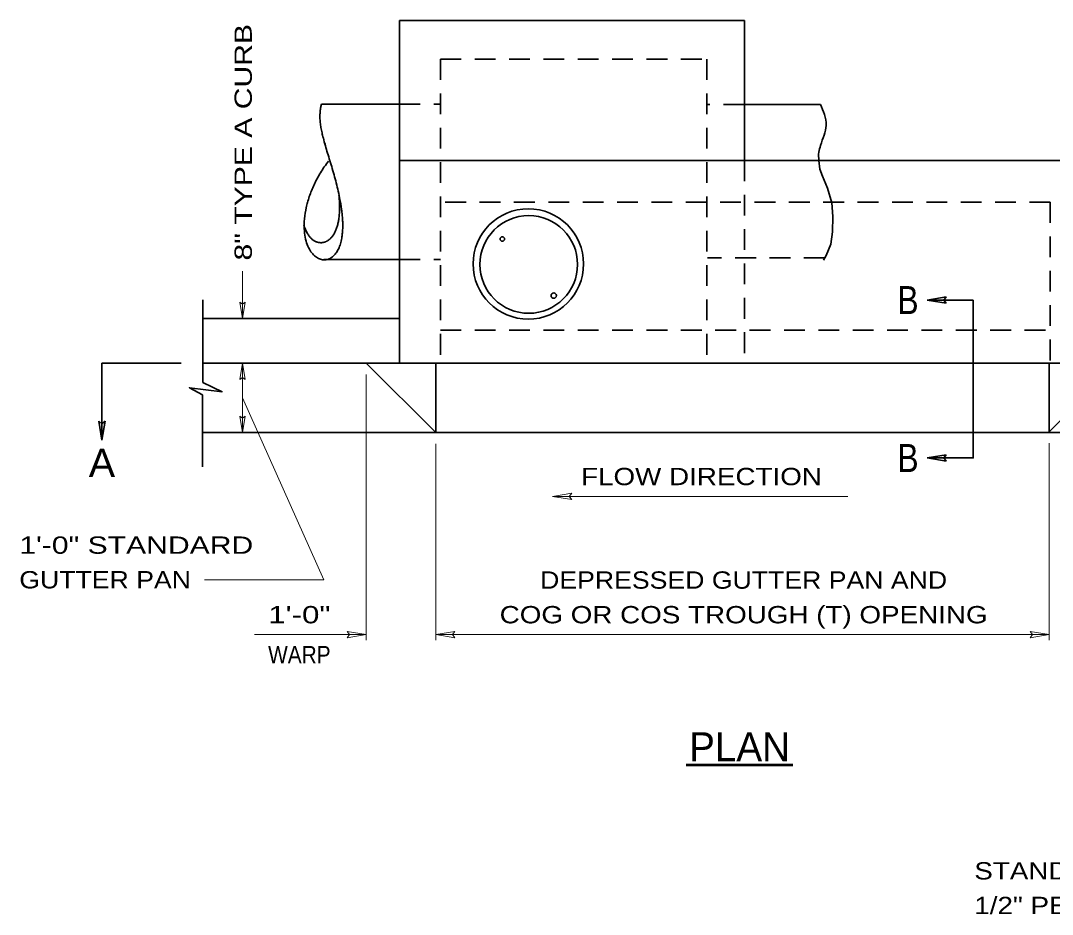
# Model space of a CAD drawing. Extents: x 16.6 to 31.7, y 5.4 to 26.
# Drawn here: x 16.65 to 24.24, y 13.28 to 19.86 of the extents above; entities that cross this region are included whole.
import ezdxf
from ezdxf.enums import TextEntityAlignment as Align

# ---------------------------------------------------------------- set-up
doc = ezdxf.new("R2010")
doc.units = 0
doc.header["$LTSCALE"] = 0.051
doc.linetypes.add('LONG_DASHED', pattern=[7.5, 6, -1.5])
doc.linetypes.add('MEDIUM_DASHED', pattern=[4.5, 3, -1.5])
for name, color, linetype, lineweight in [('1', 7, 'Continuous', 35), ('10', 7, 'Continuous', 13), ('12', 7, 'Continuous', 53), ('13', 7, 'Continuous', 53)]:
    doc.layers.add(name, color=color, linetype=linetype, lineweight=lineweight)

msp = doc.modelspace()

# ---------------------------------------------------------------- linework, layer by layer
at = {"layer": '1'}
for p, q in [((19.43833, 17.33783), (19.43833, 19.85942)), ((19.43833, 19.85942), (21.97725, 19.85942)), ((21.97725, 19.85942), (21.97725, 18.82992)), ((18.86417, 19.245), (19.43833, 19.245)), ((22.53767, 19.24225), (21.97725, 19.24225)), ((24.48625, 18.82992), (19.43833, 18.82992)), ((18.88275, 18.09975), (19.43833, 18.09975)), ((17.99208, 17.19558), (17.99208, 17.80275)), ((17.99208, 17.6655), (19.43833, 17.6655)), ((17.99208, 17.33783), (25.65375, 17.33783)), ((19.70542, 16.82675), (19.19433, 17.33783)), ((19.70542, 17.33783), (19.70542, 16.82675)), ((24.22067, 16.8315), (24.22067, 17.33783)), ((24.22067, 16.8315), (24.727, 17.33783)), ((17.98792, 16.57325), (17.98792, 17.10358)), ((25.65333, 16.82675), (17.98792, 16.82675))]:
    msp.add_line(p, q, dxfattribs=at)
at = {"layer": '1', "linetype": 'MEDIUM_DASHED'}
for p, q in [((19.73942, 19.57683), (19.73942, 17.33783)), ((19.43833, 19.245), (19.73942, 19.245)), ((21.97725, 19.24225), (21.702, 19.24225)), ((21.97725, 18.82992), (21.97725, 17.33783)), ((24.22942, 18.523), (19.73942, 18.523)), ((24.22942, 18.523), (24.22942, 17.33783)), ((19.43833, 18.09975), (19.73942, 18.09975)), ((22.56925, 18.11225), (21.70675, 18.11225)), ((19.73942, 17.5815), (24.22992, 17.5815))]:
    msp.add_line(p, q, dxfattribs=at)
msp.add_lwpolyline([(19.73942, 19.57683), (21.702, 19.57683), (21.702, 17.33783)], dxfattribs=at)
at = {"layer": '1', "linetype": 'LONG_DASHED'}
msp.add_lwpolyline([(22.52542, 18.8285), (22.53308, 18.765), (22.5535, 18.71408), (22.58925, 18.62508), (22.62242, 18.51833), (22.6275, 18.41658), (22.625, 18.30475), (22.61475, 18.21317), (22.579, 18.12925), (22.55958, 18.09533)], dxfattribs=at)
at = {"layer": '1'}
for centre, radius in [((20.38721, 18.06792), 0.40638), ((20.38983, 18.06417), 0.35949), ((20.19567, 18.25133), 0.0165), ((20.57408, 17.83454), 0.01952)]:
    msp.add_circle(centre, radius, dxfattribs=at)
for points in [[(18.86417, 19.245), (18.827, 19.09358), (18.91483, 18.85925), (19.1595, 18.28192), (19.16158, 17.88358), (18.57408, 17.913), (18.71633, 18.56783), (18.9165, 18.82575)], [(18.99325, 18.574), (18.99725, 18.53717), (19.00642, 18.39342), (18.98508, 18.274), (18.92517, 18.20125), (18.83642, 18.19292), (18.76317, 18.26392), (18.73367, 18.35692)]]:
    msp.add_open_spline(points, degree=6, dxfattribs=at)
msp.add_spline([(22.53767, 19.24225), (22.56625, 19.16925), (22.579, 19.08792), (22.56367, 19.01667), (22.53817, 18.94042), (22.52542, 18.89208), (22.52542, 18.8285)], degree=3, dxfattribs=at)
at = {"layer": '1', "lineweight": 13}
msp.add_open_spline([(18.89275, 18.95458), (18.89292, 18.95483), (18.89317, 18.95508), (18.89333, 18.95533), (18.8935, 18.95558), (18.89375, 18.95583), (18.89392, 18.95608)], degree=6, dxfattribs=at)
at = {"layer": '10'}
for p, q in [((18.28317, 17.6655), (18.28317, 18.01367)), ((18.26317, 17.7855), (18.28317, 17.6655)), ((18.26317, 17.7855), (18.28317, 17.7705)), ((18.30317, 17.7855), (18.28317, 17.6655)), ((18.30317, 17.7855), (18.28317, 17.7705)), ((18.26317, 17.21783), (18.28317, 17.33783)), ((18.30317, 17.21783), (18.28317, 17.33783)), ((18.28317, 16.82675), (18.28317, 17.33783)), ((19.19433, 15.29667), (19.19433, 17.2545)), ((18.26317, 17.21783), (18.28317, 17.23283)), ((18.30317, 17.21783), (18.28317, 17.23283)), ((18.26317, 16.94675), (18.28317, 16.82675)), ((18.26317, 16.94675), (18.28317, 16.93175)), ((18.30317, 16.94675), (18.28317, 16.82675)), ((18.30317, 16.94675), (18.28317, 16.93175)), ((19.70542, 15.29667), (19.70542, 16.74342)), ((24.22067, 15.29667), (24.22067, 16.74817)), ((20.70617, 16.37933), (20.56625, 16.35558)), ((20.70633, 16.33267), (20.56625, 16.35558)), ((20.56625, 16.35558), (22.73933, 16.35558)), ((20.70617, 16.37933), (20.68875, 16.356)), ((20.70633, 16.33267), (20.68875, 16.356)), ((19.05433, 15.36167), (19.19433, 15.33833)), ((19.05433, 15.36167), (19.07183, 15.33833)), ((19.84542, 15.3615), (19.70542, 15.33833)), ((19.84542, 15.3615), (19.82792, 15.33825)), ((24.08075, 15.36183), (24.22075, 15.33833)), ((24.08075, 15.36183), (24.09825, 15.33842)), ((19.19433, 15.33833), (18.3725, 15.33833)), ((19.05433, 15.315), (19.19433, 15.33833)), ((19.05433, 15.315), (19.07183, 15.33833)), ((19.84542, 15.31483), (19.70542, 15.33833)), ((24.22075, 15.33833), (19.70542, 15.33833)), ((19.84542, 15.31483), (19.82792, 15.33825)), ((24.08075, 15.31517), (24.09825, 15.33842)), ((24.08075, 15.31517), (24.22075, 15.33833))]:
    msp.add_line(p, q, dxfattribs=at)
at = {"layer": '10', "lineweight": 35}
for p, q in [((23.4625, 17.82508), (23.3225, 17.80175)), ((23.4625, 17.82508), (23.3225, 17.80175)), ((23.66267, 17.80175), (23.3225, 17.80175)), ((23.4625, 17.77842), (23.3225, 17.80175)), ((23.4625, 17.77842), (23.3225, 17.80175)), ((23.4625, 17.82508), (23.445, 17.80175)), ((23.4625, 17.82508), (23.445, 17.80175)), ((23.4625, 17.77842), (23.445, 17.80175)), ((23.4625, 17.77842), (23.445, 17.80175)), ((17.24842, 17.33783), (17.83275, 17.33783)), ((17.24842, 17.33783), (17.24842, 16.76925)), ((17.22508, 16.90925), (17.24842, 16.76925)), ((17.22508, 16.90925), (17.24842, 16.89175)), ((17.27175, 16.90925), (17.24842, 16.76925)), ((17.27175, 16.90925), (17.24842, 16.89175)), ((23.4625, 16.66242), (23.3225, 16.63908)), ((23.4625, 16.61575), (23.3225, 16.63908)), ((23.4625, 16.66242), (23.445, 16.63908)), ((23.4625, 16.61575), (23.445, 16.63908))]:
    msp.add_line(p, q, dxfattribs=at)
for points in [[(23.66267, 17.80175), (23.66267, 16.63908), (23.3225, 16.63908)], [(17.98792, 17.10358), (17.89267, 17.15592), (18.13308, 17.12658), (17.99208, 17.19558)]]:
    msp.add_lwpolyline(points, dxfattribs=at)
at = {"layer": '10'}
msp.add_lwpolyline([(18.28317, 17.08225), (18.88208, 15.74258), (18.00225, 15.74258)], dxfattribs=at)
at = {"layer": '12'}
msp.add_line((21.55, 14.37992), (22.33433, 14.37992), dxfattribs=at)

# ---------------------------------------------------------------- texts
at = {"layer": '12', "width": 1.3}
msp.add_text('8" TYPE A CURB', height=0.1275, rotation=90, dxfattribs=at).set_placement((18.352, 18.96396), align=Align.CENTER)
at = {"layer": '12'}
for s, width, p in [('FLOW DIRECTION', 1.2, (21.66175, 16.43892)), ('DEPRESSED GUTTER PAN AND', 1.15, (21.972, 15.67667)), ('1\'-0"', 1.35, (18.70183, 15.42167)), ('COG OR COS TROUGH (T) OPENING', 1.2, (21.97208, 15.42167)), ('WARP', 0.9, (18.70175, 15.1275))]:
    msp.add_text(s, height=0.1275, dxfattribs=dict(at, width=width)).set_placement(p, align=Align.CENTER)
for s, width, p in [('1\'-0" STANDARD', 1.3, (16.64008, 15.93383)), ('GUTTER PAN', 1.15, (16.64008, 15.67883)), ('STANDARD GUTTER PAN SLOPE=', 1.2, (23.67, 13.53558)), ('1/2" PER FOOT TOWARDS FLOW LINE.', 1.2, (23.67, 13.28058))]:
    msp.add_text(s, height=0.1275, dxfattribs=dict(at, width=width)).set_placement(p)
msp.add_text('PLAN', height=0.2125, dxfattribs=at).set_placement((21.94217, 14.40667), align=Align.CENTER)
at = {"layer": '13', "width": 0.85}
for p in [(23.26, 17.69833), (23.26, 16.53567)]:
    msp.add_text('B', height=0.2068, dxfattribs=at).set_placement(p, align=Align.RIGHT)
at = {"layer": '13', "width": 1.05}
msp.add_text('A', height=0.2068, dxfattribs=at).set_placement((17.24842, 16.49992), align=Align.CENTER)

doc.saveas('drawing.dxf')
